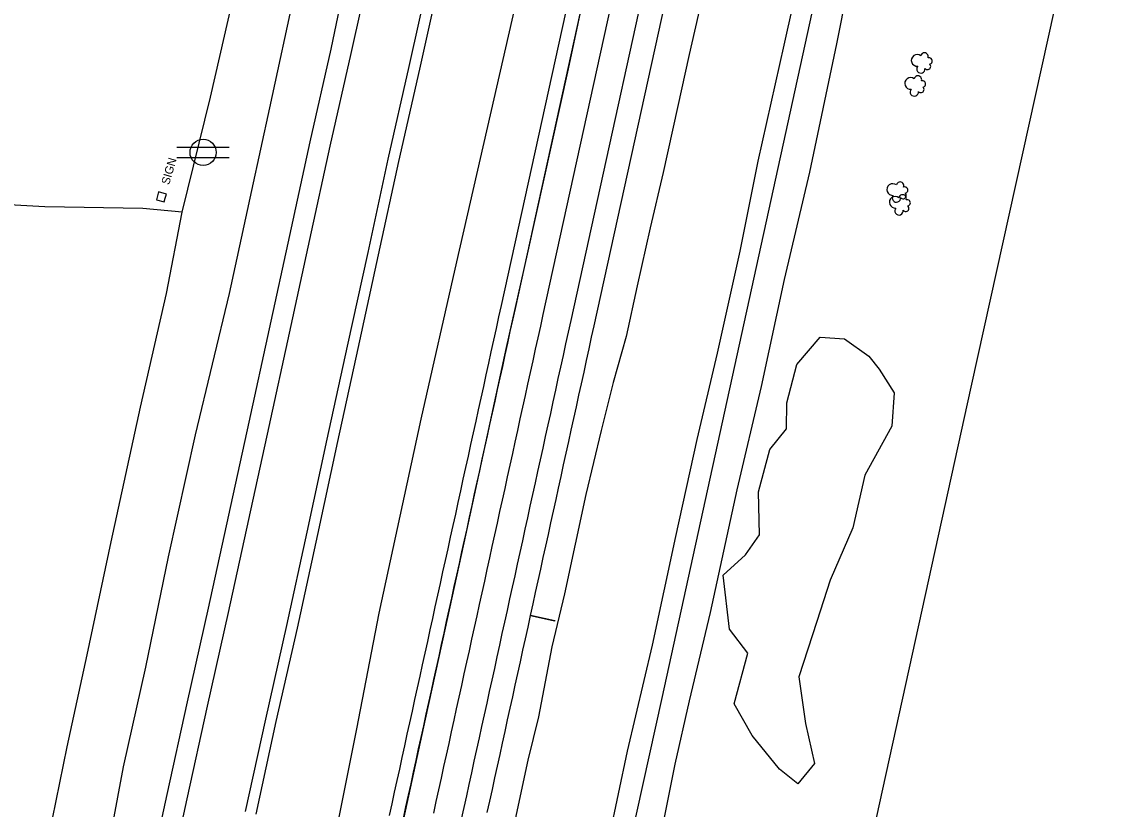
# Model space of a CAD drawing. Extents: x 14105231 to 14123593, y 8636972 to 8671693.
# Drawn here: x 14108347.1 to 14108804.9, y 8642317.8 to 8642649.6 of the extents above; entities that cross this region are included whole.
import ezdxf

# ---------------------------------------------------------------- set-up
doc = ezdxf.new("R2010")
doc.units = 0
for name, color, linetype in [('dsn3DCenterLine', 7, 'Continuous'), ('dsn3DPavementTop', 7, 'Continuous'), ('dsn3DShoulderTop', 7, 'Continuous'), ('dsnSubdrains', 7, 'Continuous'), ('PhoDrainageArrow', 7, 'Continuous'), ('PhoEdgeRoadPaved', 7, 'Continuous'), ('PhoEdgeShoulderPaved', 7, 'Continuous'), ('PhoEdgeShoulderUnpaved', 7, 'Continuous'), ('PhoFence', 7, 'Continuous'), ('PhoRailRoadTrack', 7, 'Continuous'), ('PhoRoadPoints', 7, 'Continuous'), ('PhoVegetation', 7, 'Continuous'), ('SurUtilityPoleCell', 7, 'Continuous')]:
    doc.layers.add(name, color=color, linetype=linetype)

msp = doc.modelspace()

# ---------------------------------------------------------------- linework, layer by layer
at = {"layer": 'dsn3DCenterLine'}
msp.add_lwpolyline([(14108520.69, 8642316.25), (14108521.76, 8642321.13), (14108522.84, 8642326.02), (14108523.91, 8642330.9), (14108524.98, 8642335.78), (14108526.05, 8642340.67), (14108527.13, 8642345.55), (14108528.2, 8642350.43), (14108529.27, 8642355.32), (14108530.34, 8642360.2), (14108531.42, 8642365.08), (14108532.49, 8642369.97), (14108533.56, 8642374.85), (14108534.64, 8642379.74), (14108535.71, 8642384.62), (14108536.78, 8642389.5), (14108537.85, 8642394.39), (14108538.93, 8642399.27), (14108540, 8642404.15), (14108541.07, 8642409.04), (14108542.15, 8642413.92), (14108543.22, 8642418.8), (14108544.29, 8642423.69), (14108545.36, 8642428.57), (14108546.44, 8642433.45), (14108547.51, 8642438.34), (14108548.58, 8642443.22), (14108549.66, 8642448.1), (14108550.73, 8642452.99), (14108551.8, 8642457.87), (14108552.87, 8642462.76), (14108553.95, 8642467.64), (14108555.02, 8642472.52), (14108556.09, 8642477.41), (14108557.16, 8642482.29), (14108558.24, 8642487.17), (14108559.31, 8642492.06), (14108560.38, 8642496.94), (14108561.46, 8642501.82), (14108562.53, 8642506.71), (14108563.6, 8642511.59), (14108564.67, 8642516.47), (14108565.75, 8642521.36), (14108566.82, 8642526.24), (14108653.72, 8642921.81)], dxfattribs=at)
at = {"layer": 'dsn3DPavementTop'}
for points in [[(14108507.9, 8642313.94), (14108508.97, 8642318.82), (14108510.04, 8642323.71), (14108511.11, 8642328.59), (14108512.19, 8642333.47), (14108513.26, 8642338.36), (14108514.33, 8642343.24), (14108515.41, 8642348.12), (14108516.48, 8642353.01), (14108517.55, 8642357.89), (14108518.62, 8642362.78), (14108519.7, 8642367.66), (14108520.77, 8642372.54), (14108521.84, 8642377.43), (14108522.92, 8642382.31), (14108523.99, 8642387.19), (14108525.06, 8642392.08), (14108526.13, 8642396.96), (14108527.21, 8642401.84), (14108528.28, 8642406.73), (14108529.35, 8642411.61), (14108530.43, 8642416.49), (14108531.5, 8642421.38), (14108532.57, 8642426.26), (14108533.64, 8642431.15), (14108534.72, 8642436.03), (14108535.79, 8642440.91), (14108536.86, 8642445.8), (14108537.93, 8642450.68), (14108539.01, 8642455.56), (14108540.08, 8642460.45), (14108541.15, 8642465.33), (14108542.23, 8642470.21), (14108543.3, 8642475.1), (14108544.37, 8642479.98), (14108545.44, 8642484.86), (14108546.52, 8642489.75), (14108547.59, 8642494.63), (14108548.66, 8642499.52), (14108549.74, 8642504.4), (14108550.81, 8642509.28), (14108551.88, 8642514.17), (14108552.95, 8642519.05), (14108554.03, 8642523.93), (14108555.1, 8642528.82), (14108642, 8642924.38)], [(14108532.41, 8642313.67), (14108533.48, 8642318.56), (14108534.56, 8642323.44), (14108535.63, 8642328.32), (14108536.7, 8642333.21), (14108537.77, 8642338.09), (14108538.85, 8642342.98), (14108539.92, 8642347.86), (14108540.99, 8642352.74), (14108542.07, 8642357.63), (14108543.14, 8642362.51), (14108544.21, 8642367.39), (14108545.28, 8642372.28), (14108546.36, 8642377.16), (14108547.43, 8642382.04), (14108548.5, 8642386.93), (14108549.57, 8642391.81), (14108550.65, 8642396.69), (14108551.72, 8642401.58), (14108552.79, 8642406.46), (14108553.87, 8642411.35), (14108554.94, 8642416.23), (14108556.01, 8642421.11), (14108557.08, 8642426), (14108558.16, 8642430.88), (14108559.23, 8642435.76), (14108560.3, 8642440.65), (14108561.38, 8642445.53), (14108562.45, 8642450.41), (14108563.52, 8642455.3), (14108564.59, 8642460.18), (14108565.67, 8642465.06), (14108566.74, 8642469.95), (14108567.81, 8642474.83), (14108568.89, 8642479.71), (14108569.96, 8642484.6), (14108571.03, 8642489.48), (14108572.1, 8642494.37), (14108573.18, 8642499.25), (14108574.25, 8642504.13), (14108575.32, 8642509.02), (14108576.4, 8642513.9), (14108577.47, 8642518.78), (14108578.54, 8642523.67), (14108665.44, 8642919.23)]]:
    msp.add_lwpolyline(points, dxfattribs=at)
at = {"layer": 'dsn3DShoulderTop'}
for points in [[(14108502.04, 8642315.23), (14108503.11, 8642320.11), (14108504.18, 8642324.99), (14108505.25, 8642329.88), (14108506.33, 8642334.76), (14108507.4, 8642339.65), (14108508.47, 8642344.53), (14108509.55, 8642349.41), (14108510.62, 8642354.3), (14108511.69, 8642359.18), (14108512.76, 8642364.06), (14108513.84, 8642368.95), (14108514.91, 8642373.83), (14108515.98, 8642378.71), (14108517.06, 8642383.6), (14108518.13, 8642388.48), (14108519.2, 8642393.36), (14108520.27, 8642398.25), (14108521.35, 8642403.13), (14108522.42, 8642408.02), (14108523.49, 8642412.9), (14108524.56, 8642417.78), (14108525.64, 8642422.67), (14108526.71, 8642427.55), (14108527.78, 8642432.43), (14108528.86, 8642437.32), (14108529.93, 8642442.2), (14108531, 8642447.08), (14108532.07, 8642451.97), (14108533.15, 8642456.85), (14108534.22, 8642461.73), (14108535.29, 8642466.62), (14108536.37, 8642471.5), (14108537.44, 8642476.38), (14108538.51, 8642481.27), (14108539.58, 8642486.15), (14108540.66, 8642491.04), (14108541.73, 8642495.92), (14108542.8, 8642500.8), (14108543.88, 8642505.69), (14108544.95, 8642510.57), (14108546.02, 8642515.45), (14108547.09, 8642520.34), (14108548.17, 8642525.22), (14108549.24, 8642530.11), (14108636.14, 8642925.67)], [(14108502.04, 8642315.23), (14108503.11, 8642320.11), (14108504.18, 8642324.99), (14108505.25, 8642329.88), (14108506.33, 8642334.76), (14108507.4, 8642339.65), (14108508.47, 8642344.53), (14108509.55, 8642349.41), (14108510.62, 8642354.3), (14108511.69, 8642359.18), (14108512.76, 8642364.06), (14108513.84, 8642368.95), (14108514.91, 8642373.83), (14108515.98, 8642378.71), (14108517.06, 8642383.6), (14108518.13, 8642388.48), (14108519.2, 8642393.36), (14108520.27, 8642398.25), (14108521.35, 8642403.13), (14108522.42, 8642408.02), (14108523.49, 8642412.9), (14108524.56, 8642417.78), (14108525.64, 8642422.67), (14108526.71, 8642427.55), (14108527.78, 8642432.43), (14108528.86, 8642437.32), (14108529.93, 8642442.2), (14108531, 8642447.08), (14108532.07, 8642451.97), (14108533.15, 8642456.85), (14108534.22, 8642461.73), (14108535.29, 8642466.62), (14108536.37, 8642471.5), (14108537.44, 8642476.38), (14108538.51, 8642481.27), (14108539.58, 8642486.15), (14108540.66, 8642491.04), (14108541.73, 8642495.92), (14108542.8, 8642500.8), (14108543.88, 8642505.69), (14108544.95, 8642510.57), (14108546.02, 8642515.45), (14108547.09, 8642520.34), (14108548.17, 8642525.22), (14108549.24, 8642530.11), (14108636.14, 8642925.67)], [(14108543.25, 8642316.41), (14108544.32, 8642321.3), (14108545.4, 8642326.18), (14108546.47, 8642331.06), (14108547.54, 8642335.95), (14108548.61, 8642340.83), (14108549.69, 8642345.71), (14108550.76, 8642350.6), (14108551.83, 8642355.48), (14108552.91, 8642360.36), (14108553.98, 8642365.25), (14108555.05, 8642370.13), (14108556.12, 8642375.01), (14108557.2, 8642379.9), (14108558.27, 8642384.78), (14108559.34, 8642389.67), (14108560.41, 8642394.55), (14108561.49, 8642399.43), (14108562.56, 8642404.32), (14108563.63, 8642409.2), (14108564.71, 8642414.08), (14108565.78, 8642418.97), (14108566.85, 8642423.85), (14108567.92, 8642428.73), (14108569, 8642433.62), (14108570.07, 8642438.5), (14108571.14, 8642443.38), (14108572.22, 8642448.27), (14108573.29, 8642453.15), (14108574.36, 8642458.04), (14108575.43, 8642462.92), (14108576.51, 8642467.8), (14108577.58, 8642472.69), (14108578.65, 8642477.57), (14108579.73, 8642482.45), (14108580.8, 8642487.34), (14108581.87, 8642492.22), (14108582.94, 8642497.1), (14108584.02, 8642501.99), (14108585.09, 8642506.87), (14108586.16, 8642511.75), (14108587.23, 8642516.64), (14108588.31, 8642521.52), (14108675.21, 8642917.09)]]:
    msp.add_lwpolyline(points, dxfattribs=at)
at = {"layer": 'dsnSubdrains'}
msp.add_lwpolyline([(14108561.45, 8642399.27), (14108561.52, 8642399.6), (14108571.69, 8642397.36), (14108571.61, 8642397.04)], close=True, dxfattribs=at)
at = {"layer": 'PhoDrainageArrow'}
for points in [[(14108500.42, 8642903.14), (14108502.91, 8642901.35), (14108509.58, 8642895.95), (14108509.68, 8642884.14), (14108504.99, 8642853.16), (14108497.39, 8642822.85), (14108490.16, 8642789.86), (14108481.16, 8642750.48), (14108471.71, 8642704.4), (14108462.23, 8642663.39), (14108451.43, 8642613.28), (14108443.87, 8642578.53), (14108434.48, 8642535.09), (14108420.14, 8642475.56), (14108408.71, 8642424.21), (14108399.22, 8642377.7)], [(14108597.41, 8642841), (14108594.84, 8642832.48), (14108579.07, 8642762.52), (14108563.44, 8642693.32), (14108545.95, 8642617.17), (14108530.27, 8642548.43), (14108515.21, 8642482.09), (14108497.55, 8642400.47), (14108488.07, 8642351.75), (14108473.26, 8642277.23), (14108457.34, 8642200.73), (14108440.04, 8642117.32), (14108426.79, 8642054.91), (14108412.02, 8641986.97), (14108394.39, 8641909.18), (14108382.32, 8641856.94), (14108368.25, 8641792.63)], [(14108633.24, 8642657.23), (14108628.35, 8642635.76), (14108623.35, 8642613.47), (14108617.39, 8642586.03), (14108611.84, 8642562.75), (14108606.4, 8642538.33), (14108601.76, 8642516.96), (14108596.35, 8642497.67), (14108591.24, 8642477.4), (14108584.81, 8642450.36), (14108580.22, 8642429.46), (14108575.8, 8642408.55), (14108570.39, 8642386.2), (14108564.78, 8642356.8), (14108560.4, 8642338.58), (14108555.04, 8642313.7)], [(14108399.22, 8642377.7), (14108389.84, 8642335.69), (14108380.67, 8642286.79), (14108368.16, 8642230.35), (14108357.25, 8642179.13), (14108344.96, 8642119.79), (14108335.42, 8642074.19), (14108324.83, 8642026.77), (14108315.12, 8641978.47), (14108305.83, 8641937.67), (14108295.49, 8641895.4), (14108287.82, 8641856.52), (14108279.71, 8641819.18)]]:
    msp.add_lwpolyline(points, dxfattribs=at)
at = {"layer": 'PhoEdgeRoadPaved'}
for points in [[(14108655.05, 8642984.44), (14108646.62, 8642946.06), (14108636.79, 8642900.34), (14108629.1, 8642865.95), (14108620.46, 8642826.51), (14108611.99, 8642787.87), (14108603.09, 8642748.23), (14108594.61, 8642708.71), (14108585.96, 8642670.08), (14108577.35, 8642629.76), (14108560.06, 8642551.64), (14108551.22, 8642512.37), (14108542.49, 8642472.15), (14108534.05, 8642433.28), (14108525.43, 8642394.13), (14108517.1, 8642355.82), (14108505.78, 8642304.1)], [(14108408.22, 8642282.74), (14108416.84, 8642322.21), (14108425.36, 8642361.25), (14108434.24, 8642400.66), (14108442.83, 8642439.93), (14108451.29, 8642479.08), (14108459.88, 8642518.37), (14108468.46, 8642557.78), (14108477.03, 8642597.16), (14108485.84, 8642636.18), (14108494.55, 8642675.4), (14108503.19, 8642714.56), (14108511.84, 8642753.93), (14108520.77, 8642794.08), (14108529.32, 8642832.9), (14108531.26, 8642844.56)], [(14108441.37, 8642316.82), (14108449.88, 8642355.78), (14108458.76, 8642395.19), (14108467.37, 8642434.56), (14108475.83, 8642473.7), (14108484.41, 8642512.98), (14108492.99, 8642552.4), (14108501.54, 8642591.69), (14108510.35, 8642630.67), (14108519.06, 8642669.94), (14108527.71, 8642709.13), (14108536.36, 8642748.47), (14108545.29, 8642788.62), (14108552.94, 8642828.02), (14108555.82, 8642839.24)]]:
    msp.add_lwpolyline(points, dxfattribs=at)
at = {"layer": 'PhoEdgeShoulderPaved'}
for points in [[(14108399.8, 8642284.57), (14108408.41, 8642324.04), (14108416.94, 8642363.1), (14108425.82, 8642402.52), (14108434.4, 8642441.75), (14108442.86, 8642480.9), (14108451.45, 8642520.19), (14108460.03, 8642559.6), (14108468.6, 8642599.01), (14108477.43, 8642638.05), (14108485.61, 8642677.31), (14108494.04, 8642716.62), (14108502.86, 8642756.12), (14108511.33, 8642796.67), (14108519.94, 8642835.08), (14108523.26, 8642846.52)], [(14108445.83, 8642315.82), (14108454.33, 8642354.75), (14108463.21, 8642394.16), (14108471.83, 8642433.57), (14108480.29, 8642472.71), (14108488.87, 8642511.98), (14108497.45, 8642551.41), (14108506, 8642590.67), (14108514.8, 8642629.62), (14108523.52, 8642668.91), (14108532.17, 8642708.11), (14108540.81, 8642747.45), (14108549.74, 8642787.6), (14108558.33, 8642826.6), (14108560.51, 8642838.14)]]:
    msp.add_lwpolyline(points, dxfattribs=at)
at = {"layer": 'PhoEdgeShoulderUnpaved'}
for points in [[(14108722.07, 8642881.37), (14108718.82, 8642875.51), (14108712.49, 8642843.7), (14108699.96, 8642784.66), (14108682.89, 8642705.25), (14108668.17, 8642639.76), (14108657.31, 8642590.87), (14108649.66, 8642552.9), (14108640.16, 8642510), (14108631.49, 8642473.58), (14108622.5, 8642432.73), (14108612.7, 8642386.99), (14108602.16, 8642342.35), (14108590.77, 8642288.4)], [(14108617.54, 8642312.29), (14108622.46, 8642336.79), (14108628.47, 8642363.46), (14108637.38, 8642400.69), (14108648.56, 8642452.4), (14108658.87, 8642495.96), (14108668.54, 8642540.94), (14108679.16, 8642586.18), (14108690.58, 8642640.21), (14108699.56, 8642685.57), (14108710.29, 8642733.61), (14108721.19, 8642783.45), (14108731.03, 8642821.74), (14108739.12, 8642853.73), (14108743.11, 8642868.32), (14108741.86, 8642877.29)]]:
    msp.add_lwpolyline(points, dxfattribs=at)
at = {"layer": 'PhoFence'}
for points in [[(14108414.64, 8642569.36), (14108426.66, 8642617.87), (14108438.03, 8642667.46), (14108450.65, 8642727.98), (14108464.09, 8642788.62), (14108476.19, 8642841), (14108483.95, 8642877.33), (14108490.09, 8642908.66)], [(14108250.71, 8641822.96), (14108265.14, 8641883.22), (14108282.64, 8641958.3), (14108299.86, 8642035.15), (14108318.12, 8642118.58), (14108336.37, 8642202.89), (14108353.79, 8642283.47), (14108366.22, 8642344.14), (14108374.67, 8642382.92), (14108384.82, 8642430.47), (14108397.05, 8642487.23), (14108408.02, 8642535.16), (14108414.64, 8642569.36), (14108398.05, 8642570.93), (14108356.76, 8642571.66), (14108313.98, 8642573.98), (14108270.43, 8642575.46), (14108233.95, 8642576.65), (14108189.13, 8642578.33)]]:
    msp.add_lwpolyline(points, dxfattribs=at)
at = {"layer": 'PhoRailRoadTrack'}
for points in [[(14108111.89, 8639603.32), (14108223.02, 8640108.8), (14108321.24, 8640556.85), (14108389.01, 8640865.95), (14108466.39, 8641217.04), (14108579.44, 8641730.84), (14108667.4, 8642132.59), (14108747.16, 8642495.71), (14108823.03, 8642839), (14108872.22, 8643064.53), (14108931.84, 8643335.45), (14108991.64, 8643609.03), (14109051.05, 8643877.56), (14109162.83, 8644387.73), (14109185, 8644489.59)], [(14108351.22, 8641154.7), (14108363.42, 8641212.85), (14108409.23, 8641418.25), (14108465.28, 8641674.75), (14108494.94, 8641810.65), (14108577.95, 8642187.96), (14108616.81, 8642364.08), (14108681.32, 8642658.55), (14108715.92, 8642814.39)]]:
    msp.add_lwpolyline(points, dxfattribs=at)
at = {"layer": 'PhoRoadPoints'}
msp.add_lwpolyline([(14108407.56, 8642575.31), (14108407.56, 8642575.31), (14108408.04, 8642576.95), (14108404.75, 8642577.91), (14108403.79, 8642574.62), (14108407.08, 8642573.66), (14108407.56, 8642575.31)], dxfattribs=at)
at = {"layer": 'PhoVegetation'}
msp.add_lwpolyline([(14108683.57, 8642516.73), (14108693.79, 8642516.05), (14108704.1, 8642508.71), (14108708.41, 8642503.22), (14108714.7, 8642493.26), (14108713.7, 8642479.24), (14108702.38, 8642458.61), (14108697.33, 8642436.42), (14108687.7, 8642414.32), (14108682.11, 8642396.97), (14108674.58, 8642373.56), (14108677.34, 8642353.94), (14108681.17, 8642337.1), (14108674.17, 8642328.55), (14108666.34, 8642334.72), (14108654.83, 8642348.85), (14108647.35, 8642362.24), (14108653.06, 8642383.63), (14108645.3, 8642393.66), (14108642.58, 8642416.44), (14108652.13, 8642424.96), (14108658.03, 8642433.4), (14108657.48, 8642451.49), (14108662.32, 8642469.32), (14108669.29, 8642478.07), (14108669.49, 8642489.05), (14108673.76, 8642505.2)], close=True, dxfattribs=at)
for centre, radius, start, end in [((14108724.4, 8642633.31), 2.46, 51.6938, 275.2836), ((14108727.49, 8642634.89), 1.6, 339.4869, 167.4905), ((14108729.43, 8642633.06), 1.34, 280.0129, 108.8921), ((14108725.96, 8642629.7), 1.76, 138.9711, 8.0062), ((14108728.78, 8642630.74), 1.34, 216.2389, 48.811), ((14108721.62, 8642623.61), 2.46, 51.6938, 275.2836), ((14108724.71, 8642625.19), 1.6, 339.4869, 167.4905), ((14108726.64, 8642623.37), 1.34, 280.0129, 108.8921), ((14108723.17, 8642620), 1.76, 138.9711, 8.0062), ((14108725.99, 8642621.04), 1.34, 216.2389, 48.811), ((14108717.2, 8642580.47), 1.6, 339.4869, 167.4905), ((14108714.11, 8642578.88), 2.46, 51.6938, 275.2836), ((14108718.48, 8642576.32), 1.34, 216.2389, 48.811), ((14108719.13, 8642578.64), 1.34, 280.0129, 108.8921), ((14108715.17, 8642573.53), 2.46, 51.6938, 275.2836), ((14108715.66, 8642575.28), 1.76, 138.9711, 8.0062), ((14108718.26, 8642575.11), 1.6, 339.4869, 167.4905), ((14108720.2, 8642573.28), 1.34, 280.0129, 108.8921), ((14108716.72, 8642569.92), 1.76, 138.9711, 8.0062), ((14108719.55, 8642570.96), 1.34, 216.2389, 48.811)]:
    msp.add_arc(centre, radius, start, end, dxfattribs=at)
at = {"layer": 'SurUtilityPoleCell'}
for p, q in [((14108412.49, 8642596.75), (14108434.49, 8642596.75)), ((14108412.49, 8642592.35), (14108434.49, 8642592.35))]:
    msp.add_line(p, q, dxfattribs=at)
msp.add_circle((14108423.49, 8642594.55), 5.51, dxfattribs=at)

# ---------------------------------------------------------------- texts
at = {"layer": 'PhoRoadPoints'}
msp.add_text('SIGN', height=3.499, rotation=73.7433, dxfattribs=at).set_placement((14108409.16, 8642580.68))

doc.saveas('drawing.dxf')
